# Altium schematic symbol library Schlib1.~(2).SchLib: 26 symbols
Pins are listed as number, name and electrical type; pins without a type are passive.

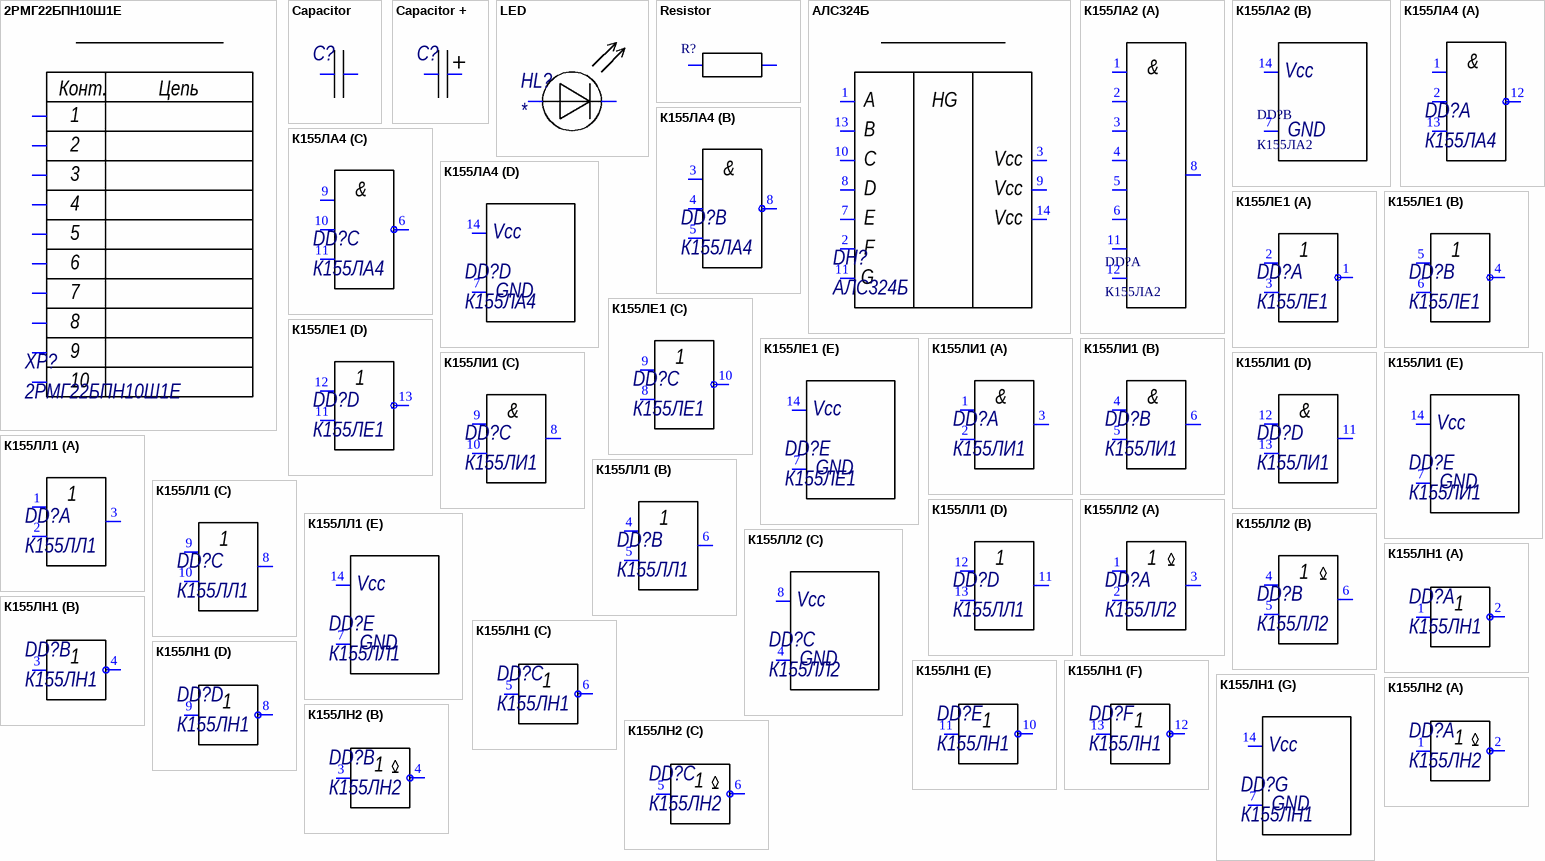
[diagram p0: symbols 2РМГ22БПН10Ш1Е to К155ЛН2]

## 2РМГ22БПН10Ш1Е
designator XP?
pins: 1, 1, 1, 1, 1, 1, 1, 1, 1, 1

## Capacitor
designator C?  (value not drawn)
pins: 1, 2

## Capacitor +
designator C?  (value not drawn)
pins: 1, 2

## LED
designator HL?
pins: 1, 2

## Resistor
designator R?  (value not drawn)
pins: 1, 2

## АЛС324Б
designator DH?
pins: 1, 2, 3, 7, 8, 9, 10, 11, 13, 14

## К155ЛА2
designator DD?
part A pins: 1, 2, 3, 4, 5, 6, 8, 11, 12
part B pins: 7, 14

## К155ЛА4
designator DD?
part A pins: 1, 2, 12, 13
part B pins: 3, 4, 5, 8
part C pins: 6, 9, 10, 11
part D pins: 7, 14

## К155ЛЕ1
designator DD?
part A pins: 1, 2, 3
part B pins: 4, 5, 6
part C pins: 8, 9, 10
part D pins: 11, 12, 13
part E pins: 7, 14

## К155ЛИ1
designator DD?
part A pins: 1, 2, 3
part B pins: 4, 5, 6
part C pins: 8, 9, 10
part D pins: 11, 12, 13
part E pins: 7, 14

## К155ЛЛ1
designator DD?
part A pins: 1, 2, 3
part B pins: 4, 5, 6
part C pins: 8, 9, 10
part D pins: 11, 12, 13
part E pins: 7, 14

## К155ЛЛ2
designator DD?
part A pins: 1, 2, 3
part B pins: 4, 5, 6
part C pins: 4, 8

## К155ЛН1
designator DD?
part A pins: 1, 2
part B pins: 3, 4
part C pins: 5, 6
part D pins: 8, 9
part E pins: 10, 11
part F pins: 12, 13
part G pins: 7, 14

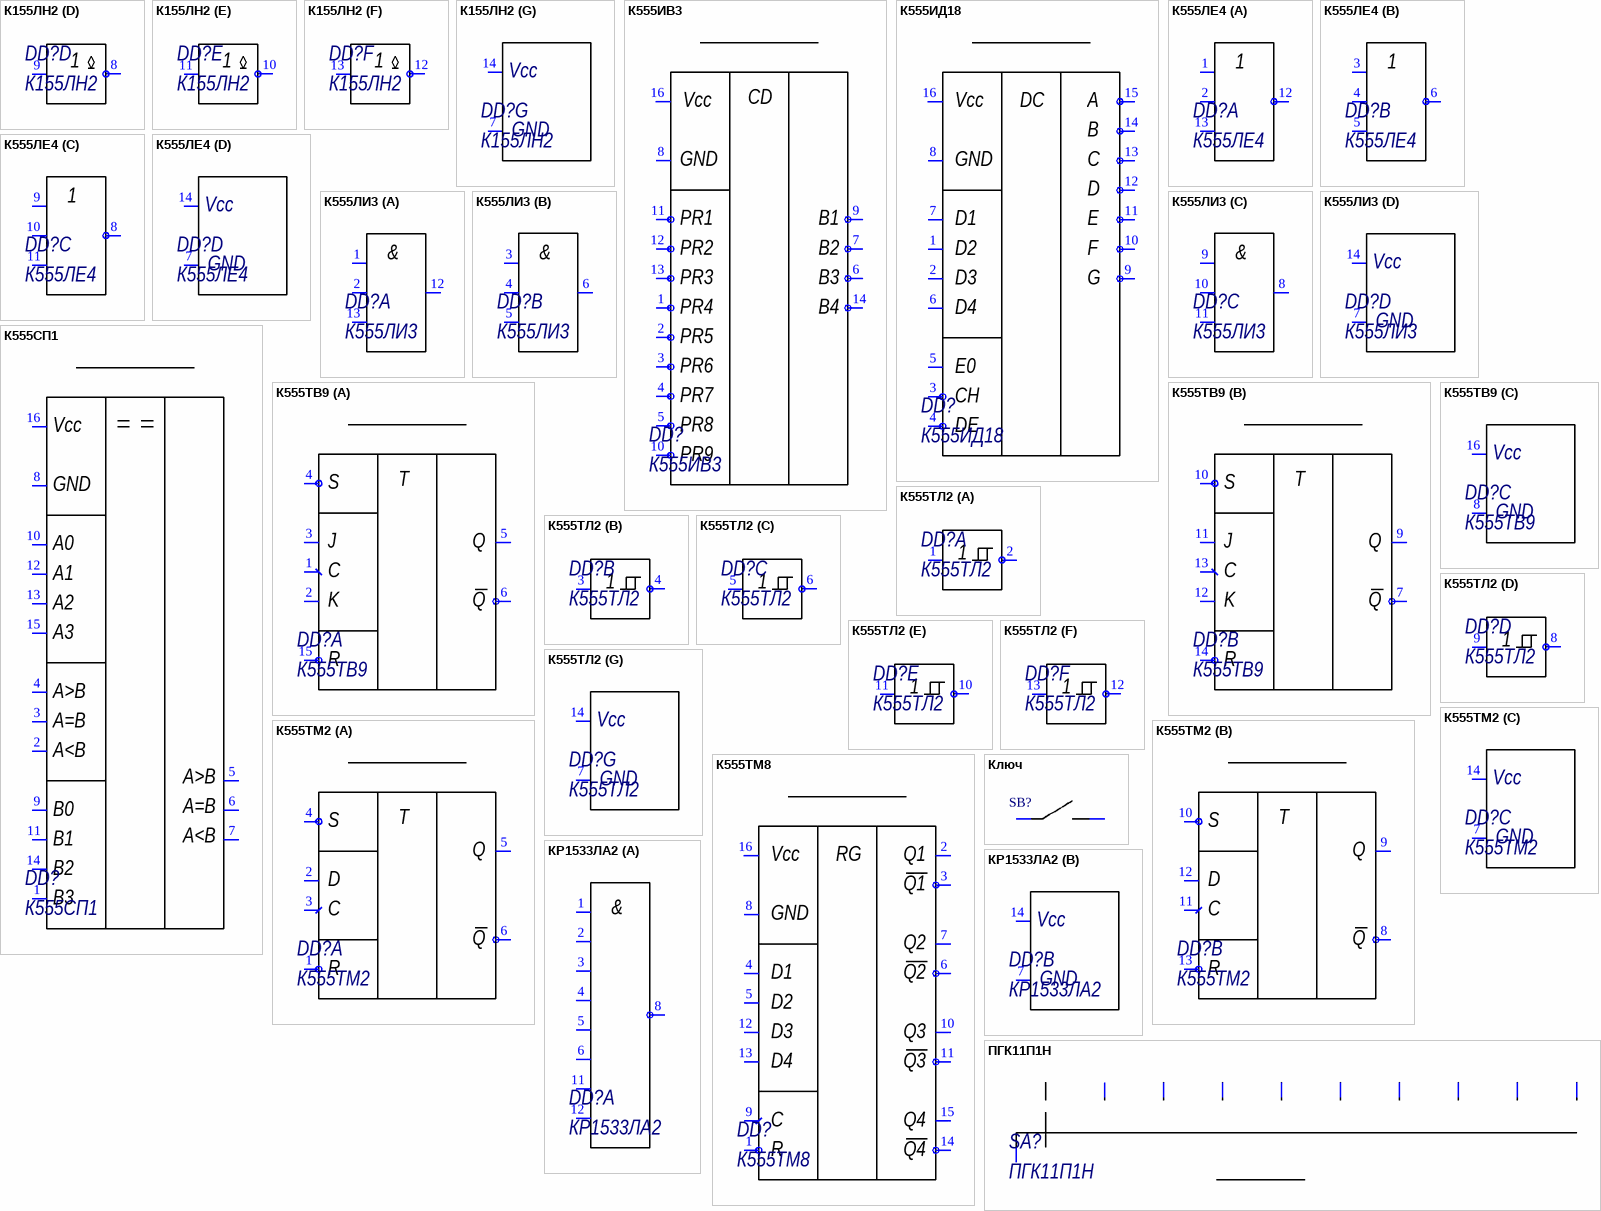
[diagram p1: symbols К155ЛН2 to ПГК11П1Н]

## К155ЛН2
designator DD?
part A pins: 1, 2
part B pins: 3, 4
part C pins: 5, 6
part D pins: 8, 9
part E pins: 10, 11
part F pins: 12, 13
part G pins: 7, 14

## К555ИВ3
designator DD?
pins: 1, 2, 3, 4, 5, 6, 7, 8, 9, 10, 11, 12 ш, 13, 14, 16

## К555ИД18
designator DD?
pins: 1, 2, 3, 4, 5, 6, 7, 8, 9, 10, 11, 12, 13, 14, 15, 16

## К555ЛЕ4
designator DD?
part A pins: 1, 2, 12, 13
part B pins: 3, 4, 5, 6
part C pins: 8, 9, 10, 11
part D pins: 7, 14

## К555ЛИ3
designator DD?
part A pins: 1, 2, 12, 13
part B pins: 3, 4, 5, 6
part C pins: 8, 9, 10, 11
part D pins: 7, 14

## К555СП1
designator DD?
pins: 1, 2, 3, 4, 5, 6, 7, 8, 9, 10, 11, 12, 13, 14, 15, 16

## К555ТВ9
designator DD?
part A pins: 1, 2, 3, 4, 5, 6, 15
part B pins: 7, 9, 10, 11, 12, 13, 14
part C pins: 8, 16

## К555ТЛ2
designator DD?
part A pins: 1, 2
part B pins: 3, 4
part C pins: 5, 6
part D pins: 8, 9
part E pins: 10, 11
part F pins: 12, 13
part G pins: 7, 14

## К555ТМ2
designator DD?
part A pins: 1, 2, 3, 4, 5, 6
part B pins: 8, 9, 10, 11, 12, 13
part C pins: 7, 14

## К555ТМ8
designator DD?
pins: 1, 2, 3, 4, 5, 6, 7, 8, 9, 10, 11, 12, 13, 14, 15, 16

## Ключ
designator SB?  (value not drawn)
pins: 1, 2

## КР1533ЛА2
designator DD?
part A pins: 1, 2, 3, 4, 5, 6, 8, 11, 12
part B pins: 7, 14

## ПГК11П1Н
designator SA?
pins: 1, 2, 2, 3, 4, 5, 6, 7, 8, 9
